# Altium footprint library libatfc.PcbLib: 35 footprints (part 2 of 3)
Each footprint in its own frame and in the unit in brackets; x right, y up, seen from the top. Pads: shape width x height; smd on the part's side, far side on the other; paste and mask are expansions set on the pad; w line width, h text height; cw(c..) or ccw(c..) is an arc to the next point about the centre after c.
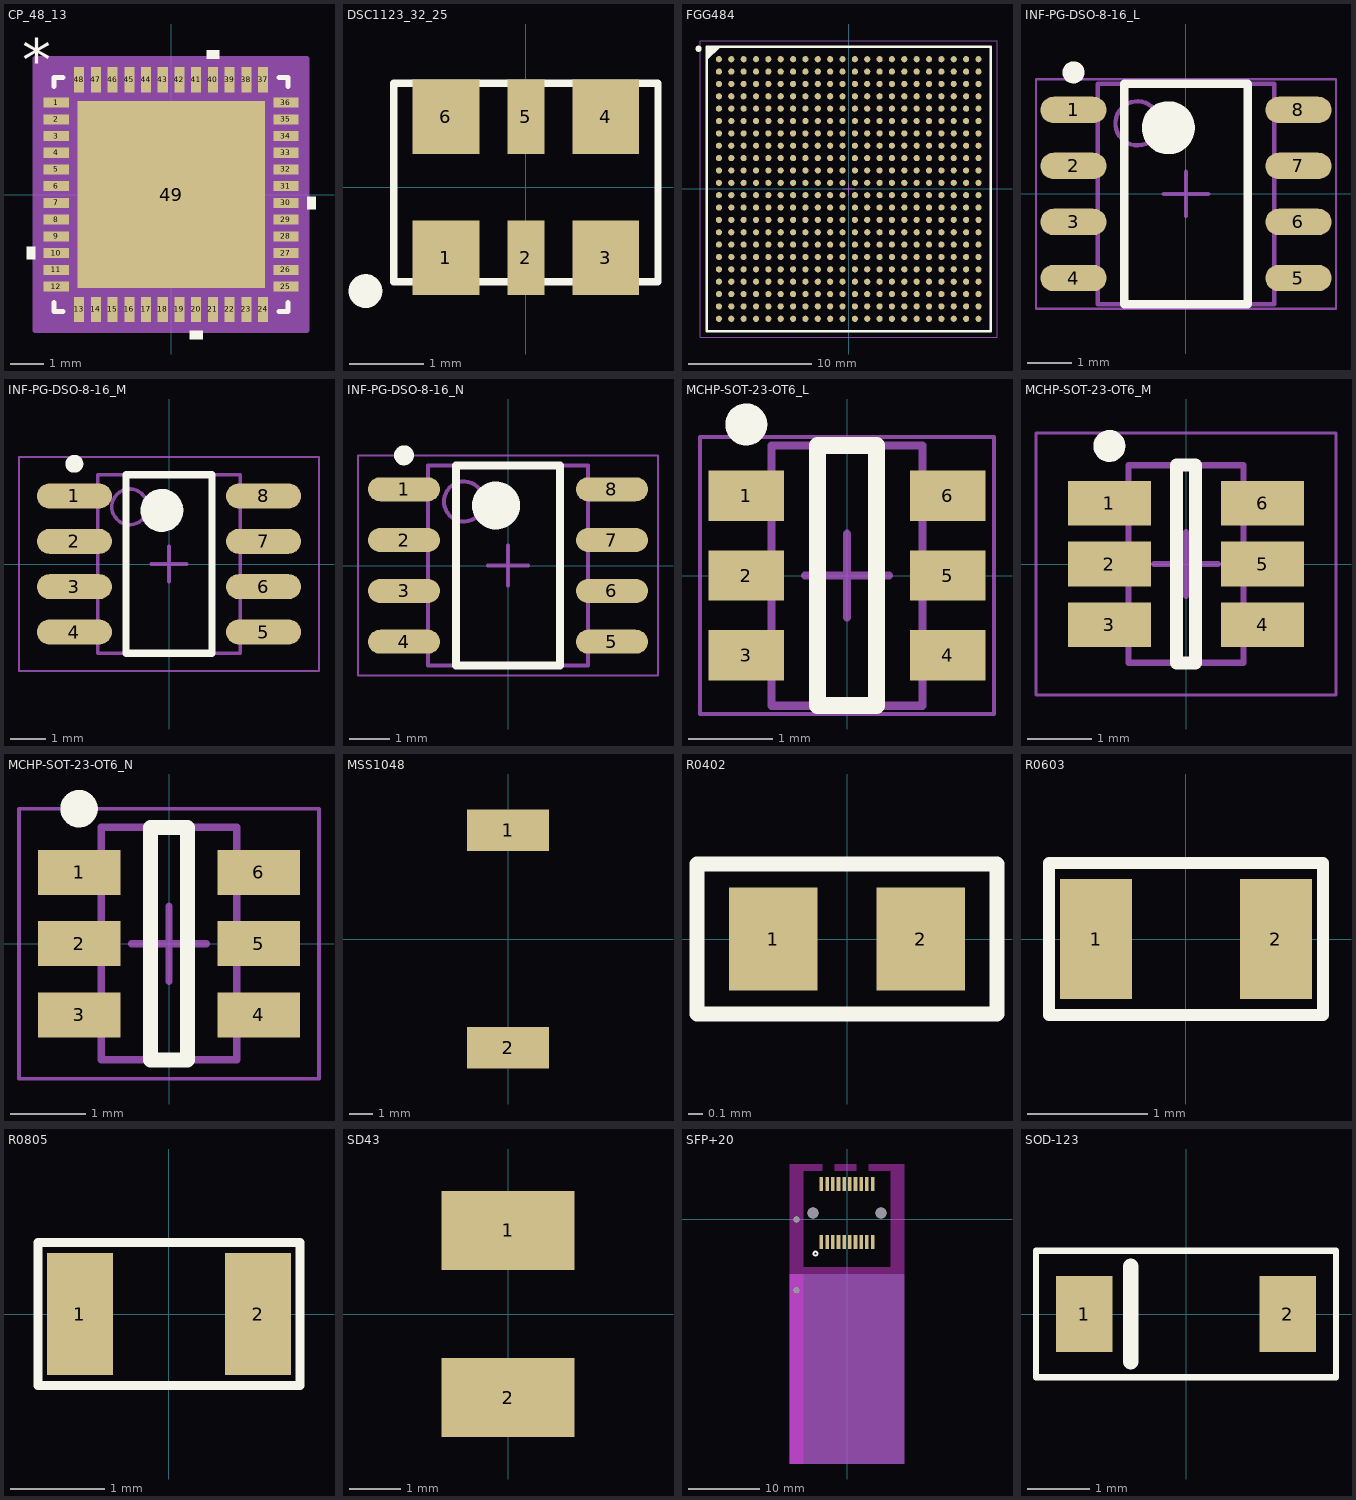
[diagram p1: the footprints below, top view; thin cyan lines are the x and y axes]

## CP_48_13 [mm]
pads (49):
  rect 0.755x0.3 smd: 1(-3.433,2.75) 2(-3.433,2.25) 3(-3.433,1.75) 4(-3.433,1.25) 5(-3.433,0.75) 6(-3.433,0.25) 7(-3.433,-0.25) 8(-3.433,-0.75) 9(-3.433,-1.25) 10(-3.433,-1.75) 11(-3.433,-2.25) 12(-3.433,-2.75) 25(3.433,-2.75) 26(3.433,-2.25) 27(3.433,-1.75) 28(3.433,-1.25) 29(3.433,-0.75) 30(3.433,-0.25) 31(3.433,0.25) 32(3.433,0.75) 33(3.433,1.25) 34(3.433,1.75) 35(3.433,2.25) 36(3.433,2.75)
  rect 0.3x0.755 smd: 13(-2.75,-3.433) 14(-2.25,-3.433) 15(-1.75,-3.433) 16(-1.25,-3.433) 17(-0.75,-3.433) 18(-0.25,-3.433) 19(0.25,-3.433) 20(0.75,-3.433) 21(1.25,-3.433) 22(1.75,-3.433) 23(2.25,-3.433) 24(2.75,-3.433) 37(2.75,3.433) 38(2.25,3.433) 39(1.75,3.433) 40(1.25,3.433) 41(0.75,3.433) 42(0.25,3.433) 43(-0.25,3.433) 44(-0.75,3.433) 45(-1.25,3.433) 46(-1.75,3.433) 47(-2.25,3.433) 48(-2.75,3.433)
  rect 5.6x5.6 smd mask-2.781: 49(0,0)
Top Overlay:
  region: -4.064,-1.559 -4.318,-1.559 -4.318,-1.94 -4.064,-1.94
  region: 0.941,-4.064 0.56,-4.064 0.56,-4.318 0.941,-4.318
  region: 4.064,-0.059 4.318,-0.059 4.318,-0.44 4.064,-0.44
  region: 1.441,4.064 1.06,4.064 1.06,4.318 1.441,4.318
  lines w0.152: -3.5,-3.233 -3.5,-3.5 -3.233,-3.5 ; -3.5,3.233 -3.5,3.5 -3.233,3.5 ; 3.233,-3.5 3.5,-3.5 3.5,-3.233 ; 3.233,3.5 3.5,3.5 3.5,3.233
  text "*" at -4.445,3.381 h1.27
Mechanical 13:
  text "*" at -4.445,3.381 h1.27
Mechanical 15:
  region: 4.064,-4.064 -4.064,-4.064 -4.064,4.064 4.064,4.064
  lines w0.152: -4.064,-4.064 -4.064,4.064 4.064,4.064 4.064,-4.064 -4.064,-4.064
3D body: height 0.25, standoff 0, extent 0,0 0.254,0.254

## DSC1123_32_25 [mm]
pads (6):
  rect 0.9x1 smd: 1(-1.075,-0.95) 3(1.075,-0.95) 4(1.075,0.95) 6(-1.075,0.95)
  rect 0.5x1 smd: 2(0,-0.95) 5(0,0.95)
Top Overlay:
  circle w0.254: c-2.159,-1.397 r0.1
  lines w0.1: -1.778,-1.27 -1.778,1.397 1.778,1.397 1.778,-1.27 -1.778,-1.27
3D body: height 0.85, standoff 0, extent -1.778,-1.27 1.778,1.397

## FGG484 [mm] "BGA, 484-Balls, Body 23x23mm, Pitch 1mm"
height 2.6
pads (484):
  round 0.5 smd: A1(-10.5,10.5) A2(-9.5,10.5) A3(-8.5,10.5) A4(-7.5,10.5) A5(-6.5,10.5) A6(-5.5,10.5) A7(-4.5,10.5) A8(-3.5,10.5) A9(-2.5,10.5) A10(-1.5,10.5) A11(-0.5,10.5) A12(0.5,10.5) A13(1.5,10.5) A14(2.5,10.5) A15(3.5,10.5) A16(4.5,10.5) A17(5.5,10.5) A18(6.5,10.5) A19(7.5,10.5) A20(8.5,10.5) A21(9.5,10.5) A22(10.5,10.5) AA1(-10.5,-9.5) AA2(-9.5,-9.5) AA3(-8.5,-9.5) AA4(-7.5,-9.5) AA5(-6.5,-9.5) AA6(-5.5,-9.5) AA7(-4.5,-9.5) AA8(-3.5,-9.5) AA9(-2.5,-9.5) AA10(-1.5,-9.5) AA11(-0.5,-9.5) AA12(0.5,-9.5) AA13(1.5,-9.5) AA14(2.5,-9.5) AA15(3.5,-9.5) AA16(4.5,-9.5) AA17(5.5,-9.5) AA18(6.5,-9.5) AA19(7.5,-9.5) AA20(8.5,-9.5) AA21(9.5,-9.5) AA22(10.5,-9.5) AB1(-10.5,-10.5) AB2(-9.5,-10.5) AB3(-8.5,-10.5) AB4(-7.5,-10.5) AB5(-6.5,-10.5) AB6(-5.5,-10.5) AB7(-4.5,-10.5) AB8(-3.5,-10.5) AB9(-2.5,-10.5) AB10(-1.5,-10.5) AB11(-0.5,-10.5) AB12(0.5,-10.5) AB13(1.5,-10.5) AB14(2.5,-10.5) AB15(3.5,-10.5) AB16(4.5,-10.5) AB17(5.5,-10.5) AB18(6.5,-10.5) AB19(7.5,-10.5) AB20(8.5,-10.5) AB21(9.5,-10.5) AB22(10.5,-10.5) B1(-10.5,9.5) B2(-9.5,9.5) B3(-8.5,9.5) B4(-7.5,9.5) B5(-6.5,9.5) B6(-5.5,9.5) B7(-4.5,9.5) B8(-3.5,9.5) B9(-2.5,9.5) B10(-1.5,9.5) B11(-0.5,9.5) B12(0.5,9.5) B13(1.5,9.5) B14(2.5,9.5) B15(3.5,9.5) B16(4.5,9.5) B17(5.5,9.5) B18(6.5,9.5) B19(7.5,9.5) B20(8.5,9.5) B21(9.5,9.5) B22(10.5,9.5) C1(-10.5,8.5) C2(-9.5,8.5) C3(-8.5,8.5) C4(-7.5,8.5) C5(-6.5,8.5) C6(-5.5,8.5) C7(-4.5,8.5) C8(-3.5,8.5) C9(-2.5,8.5) C10(-1.5,8.5) C11(-0.5,8.5) C12(0.5,8.5) C13(1.5,8.5) C14(2.5,8.5) C15(3.5,8.5) C16(4.5,8.5) C17(5.5,8.5) C18(6.5,8.5) C19(7.5,8.5) C20(8.5,8.5) C21(9.5,8.5) C22(10.5,8.5) D1(-10.5,7.5) D2(-9.5,7.5) D3(-8.5,7.5) D4(-7.5,7.5) D5(-6.5,7.5) D6(-5.5,7.5) D7(-4.5,7.5) D8(-3.5,7.5) D9(-2.5,7.5) D10(-1.5,7.5) D11(-0.5,7.5) D12(0.5,7.5) D13(1.5,7.5) D14(2.5,7.5) D15(3.5,7.5) D16(4.5,7.5) D17(5.5,7.5) D18(6.5,7.5) D19(7.5,7.5) D20(8.5,7.5) D21(9.5,7.5) D22(10.5,7.5) E1(-10.5,6.5) E2(-9.5,6.5) E3(-8.5,6.5) E4(-7.5,6.5) E5(-6.5,6.5) E6(-5.5,6.5) E7(-4.5,6.5) E8(-3.5,6.5) E9(-2.5,6.5) E10(-1.5,6.5) E11(-0.5,6.5) E12(0.5,6.5) E13(1.5,6.5) E14(2.5,6.5) E15(3.5,6.5) E16(4.5,6.5) E17(5.5,6.5) E18(6.5,6.5) E19(7.5,6.5) E20(8.5,6.5) E21(9.5,6.5) E22(10.5,6.5) F1(-10.5,5.5) F2(-9.5,5.5) F3(-8.5,5.5) F4(-7.5,5.5) F5(-6.5,5.5) F6(-5.5,5.5) F7(-4.5,5.5) F8(-3.5,5.5) F9(-2.5,5.5) F10(-1.5,5.5) F11(-0.5,5.5) F12(0.5,5.5) F13(1.5,5.5) F14(2.5,5.5) F15(3.5,5.5) F16(4.5,5.5) F17(5.5,5.5) F18(6.5,5.5) F19(7.5,5.5) F20(8.5,5.5) F21(9.5,5.5) F22(10.5,5.5) G1(-10.5,4.5) G2(-9.5,4.5) G3(-8.5,4.5) G4(-7.5,4.5) G5(-6.5,4.5) G6(-5.5,4.5) G7(-4.5,4.5) G8(-3.5,4.5) G9(-2.5,4.5) G10(-1.5,4.5) G11(-0.5,4.5) G12(0.5,4.5) G13(1.5,4.5) G14(2.5,4.5) G15(3.5,4.5) G16(4.5,4.5) G17(5.5,4.5) G18(6.5,4.5) G19(7.5,4.5) G20(8.5,4.5) G21(9.5,4.5) G22(10.5,4.5) H1(-10.5,3.5) H2(-9.5,3.5) H3(-8.5,3.5) H4(-7.5,3.5) H5(-6.5,3.5) H6(-5.5,3.5) H7(-4.5,3.5) H8(-3.5,3.5) H9(-2.5,3.5) H10(-1.5,3.5) H11(-0.5,3.5) H12(0.5,3.5) H13(1.5,3.5) H14(2.5,3.5) H15(3.5,3.5) H16(4.5,3.5) H17(5.5,3.5) H18(6.5,3.5) H19(7.5,3.5) H20(8.5,3.5) H21(9.5,3.5) H22(10.5,3.5) J1(-10.5,2.5) J2(-9.5,2.5) J3(-8.5,2.5) J4(-7.5,2.5) J5(-6.5,2.5) J6(-5.5,2.5) J7(-4.5,2.5) J8(-3.5,2.5) J9(-2.5,2.5) J10(-1.5,2.5) J11(-0.5,2.5) J12(0.5,2.5) J13(1.5,2.5) J14(2.5,2.5) J15(3.5,2.5) J16(4.5,2.5) J17(5.5,2.5) J18(6.5,2.5) J19(7.5,2.5) J20(8.5,2.5) J21(9.5,2.5) J22(10.5,2.5) K1(-10.5,1.5) K2(-9.5,1.5) K3(-8.5,1.5) K4(-7.5,1.5) K5(-6.5,1.5) K6(-5.5,1.5) K7(-4.5,1.5) K8(-3.5,1.5) K9(-2.5,1.5) K10(-1.5,1.5) K11(-0.5,1.5) K12(0.5,1.5) K13(1.5,1.5) K14(2.5,1.5) K15(3.5,1.5) K16(4.5,1.5) K17(5.5,1.5) K18(6.5,1.5) K19(7.5,1.5) K20(8.5,1.5) K21(9.5,1.5) K22(10.5,1.5) L1(-10.5,0.5) L2(-9.5,0.5) L3(-8.5,0.5) L4(-7.5,0.5) L5(-6.5,0.5) L6(-5.5,0.5) L7(-4.5,0.5) L8(-3.5,0.5) L9(-2.5,0.5) L10(-1.5,0.5) L11(-0.5,0.5) L12(0.5,0.5) L13(1.5,0.5) L14(2.5,0.5) L15(3.5,0.5) L16(4.5,0.5) L17(5.5,0.5) L18(6.5,0.5) L19(7.5,0.5) L20(8.5,0.5) L21(9.5,0.5) L22(10.5,0.5) M1(-10.5,-0.5) M2(-9.5,-0.5) M3(-8.5,-0.5) M4(-7.5,-0.5) M5(-6.5,-0.5) M6(-5.5,-0.5) M7(-4.5,-0.5) M8(-3.5,-0.5) M9(-2.5,-0.5) M10(-1.5,-0.5) M11(-0.5,-0.5) M12(0.5,-0.5) M13(1.5,-0.5) M14(2.5,-0.5) M15(3.5,-0.5) M16(4.5,-0.5) M17(5.5,-0.5) M18(6.5,-0.5) M19(7.5,-0.5) M20(8.5,-0.5) M21(9.5,-0.5) M22(10.5,-0.5) N1(-10.5,-1.5) N2(-9.5,-1.5) N3(-8.5,-1.5) N4(-7.5,-1.5) N5(-6.5,-1.5) N6(-5.5,-1.5) N7(-4.5,-1.5) N8(-3.5,-1.5) N9(-2.5,-1.5) N10(-1.5,-1.5) N11(-0.5,-1.5) N12(0.5,-1.5) N13(1.5,-1.5) N14(2.5,-1.5) N15(3.5,-1.5) N16(4.5,-1.5) N17(5.5,-1.5) N18(6.5,-1.5) N19(7.5,-1.5) N20(8.5,-1.5) N21(9.5,-1.5) N22(10.5,-1.5) P1(-10.5,-2.5) P2(-9.5,-2.5) P3(-8.5,-2.5) P4(-7.5,-2.5) P5(-6.5,-2.5) P6(-5.5,-2.5) P7(-4.5,-2.5) P8(-3.5,-2.5) P9(-2.5,-2.5) P10(-1.5,-2.5) P11(-0.5,-2.5) P12(0.5,-2.5) P13(1.5,-2.5) P14(2.5,-2.5) P15(3.5,-2.5) P16(4.5,-2.5) P17(5.5,-2.5) P18(6.5,-2.5) P19(7.5,-2.5) P20(8.5,-2.5) P21(9.5,-2.5) P22(10.5,-2.5) R1(-10.5,-3.5) R2(-9.5,-3.5) R3(-8.5,-3.5) R4(-7.5,-3.5) R5(-6.5,-3.5) R6(-5.5,-3.5) R7(-4.5,-3.5) R8(-3.5,-3.5) R9(-2.5,-3.5) R10(-1.5,-3.5) R11(-0.5,-3.5) R12(0.5,-3.5) R13(1.5,-3.5) R14(2.5,-3.5) R15(3.5,-3.5) R16(4.5,-3.5) R17(5.5,-3.5) R18(6.5,-3.5) R19(7.5,-3.5) R20(8.5,-3.5) R21(9.5,-3.5) R22(10.5,-3.5) T1(-10.5,-4.5) T2(-9.5,-4.5) T3(-8.5,-4.5) T4(-7.5,-4.5) T5(-6.5,-4.5) T6(-5.5,-4.5) T7(-4.5,-4.5) T8(-3.5,-4.5) T9(-2.5,-4.5) T10(-1.5,-4.5) T11(-0.5,-4.5) T12(0.5,-4.5) T13(1.5,-4.5) T14(2.5,-4.5) T15(3.5,-4.5) T16(4.5,-4.5) T17(5.5,-4.5) T18(6.5,-4.5) T19(7.5,-4.5) T20(8.5,-4.5) T21(9.5,-4.5) T22(10.5,-4.5) U1(-10.5,-5.5) U2(-9.5,-5.5) U3(-8.5,-5.5) U4(-7.5,-5.5) U5(-6.5,-5.5) U6(-5.5,-5.5) U7(-4.5,-5.5) U8(-3.5,-5.5) U9(-2.5,-5.5) U10(-1.5,-5.5) U11(-0.5,-5.5) U12(0.5,-5.5) U13(1.5,-5.5) U14(2.5,-5.5) U15(3.5,-5.5) U16(4.5,-5.5) U17(5.5,-5.5) U18(6.5,-5.5) U19(7.5,-5.5) U20(8.5,-5.5) U21(9.5,-5.5) U22(10.5,-5.5) V1(-10.5,-6.5) V2(-9.5,-6.5) V3(-8.5,-6.5) V4(-7.5,-6.5) V5(-6.5,-6.5) V6(-5.5,-6.5) V7(-4.5,-6.5) V8(-3.5,-6.5) V9(-2.5,-6.5) V10(-1.5,-6.5) V11(-0.5,-6.5) V12(0.5,-6.5) V13(1.5,-6.5) V14(2.5,-6.5) V15(3.5,-6.5) V16(4.5,-6.5) V17(5.5,-6.5) V18(6.5,-6.5) V19(7.5,-6.5) V20(8.5,-6.5) V21(9.5,-6.5) V22(10.5,-6.5) W1(-10.5,-7.5) W2(-9.5,-7.5) W3(-8.5,-7.5) W4(-7.5,-7.5) W5(-6.5,-7.5) W6(-5.5,-7.5) W7(-4.5,-7.5) W8(-3.5,-7.5) W9(-2.5,-7.5) W10(-1.5,-7.5) W11(-0.5,-7.5) W12(0.5,-7.5) W13(1.5,-7.5) W14(2.5,-7.5) W15(3.5,-7.5) W16(4.5,-7.5) W17(5.5,-7.5) W18(6.5,-7.5) W19(7.5,-7.5) W20(8.5,-7.5) W21(9.5,-7.5) W22(10.5,-7.5) Y1(-10.5,-8.5) Y2(-9.5,-8.5) Y3(-8.5,-8.5) Y4(-7.5,-8.5) Y5(-6.5,-8.5) Y6(-5.5,-8.5) Y7(-4.5,-8.5) Y8(-3.5,-8.5) Y9(-2.5,-8.5) Y10(-1.5,-8.5) Y11(-0.5,-8.5) Y12(0.5,-8.5) Y13(1.5,-8.5) Y14(2.5,-8.5) Y15(3.5,-8.5) Y16(4.5,-8.5) Y17(5.5,-8.5) Y18(6.5,-8.5) Y19(7.5,-8.5) Y20(8.5,-8.5) Y21(9.5,-8.5) Y22(10.5,-8.5)
Top Overlay:
  circle w0.25: c-12.15,11.35 r0.125
  region: -10.5,11.5 -11.5,10.5 -11.5,11.5
  lines w0.2: -11.5,10.5 -10.5,11.5 ; -11.5,-11.5 11.5,-11.5 11.5,11.5 -11.5,11.5 -11.5,-11.5
Mechanical 13:
  lines w0.1: -11.5,-11.5 11.5,-11.5 11.5,11.5 -11.5,11.5 -11.5,-11.5
Mechanical 15:
  lines w0.05: -12,-12 12,-12 12,12 -12,12 -12,-12
  lines w0.1: -0.5,0 0.5,0 ; 0,-0.5 0,0.5
3D body: height 2.6, standoff 0.35, extent -11.5,-11.5 11.5,11.5

## INF-PG-DSO-8-16_L [mm] "SOP, 8-Leads, Body 4.9x3.9mm, Pitch 1.27mm, IPC High Density"
height 1.75
pads (8):
  oval 1.5x0.6 smd: 1(-2.55,1.905) 2(-2.55,0.635) 3(-2.55,-0.635) 4(-2.55,-1.905) 5(2.55,-1.905) 6(2.55,-0.635) 7(2.55,0.635) 8(2.55,1.905)
Top Overlay:
  circle w0.6: c-0.4,1.5 r0.3
  circle w0.25: c-2.55,2.755 r0.125
  lines w0.2: -1.4,-2.5 1.4,-2.5 1.4,2.5 -1.4,2.5 -1.4,-2.5
Mechanical 13:
  circle w0.1: c-1.1,1.6 r0.5
  lines w0.1: -2,-2.5 2,-2.5 2,2.5 -2,2.5 -2,-2.5
Mechanical 15:
  lines w0.05: -3.4,-2.6 3.4,-2.6 3.4,2.6 -3.4,2.6 -3.4,-2.6
  lines w0.1: -0.5,0 0.5,0 ; 0,-0.5 0,0.5
3D body: height 1.75, standoff 0.11, extent -2,-2.5 2,2.5

## INF-PG-DSO-8-16_M [mm] "SOP, 8-Leads, Body 4.9x3.9mm, Pitch 1.27mm, IPC Low Density"
height 1.75
pads (8):
  oval 2.1x0.7 smd: 1(-2.65,1.905) 2(-2.65,0.635) 3(-2.65,-0.635) 4(-2.65,-1.905) 5(2.65,-1.905) 6(2.65,-0.635) 7(2.65,0.635) 8(2.65,1.905)
Top Overlay:
  circle w0.25: c-2.65,2.805 r0.125
  circle w0.6: c-0.2,1.5 r0.3
  lines w0.2: -1.2,-2.5 -1.2,2.5 1.2,2.5 1.2,-2.5 -1.2,-2.5
Mechanical 13:
  circle w0.1: c-1.1,1.6 r0.5
  lines w0.1: -2,-2.5 -2,2.5 2,2.5 2,-2.5 -2,-2.5
Mechanical 15:
  lines w0.05: -4.2,-3 -4.2,3 4.2,3 4.2,-3 -4.2,-3
  lines w0.1: -0.5,0 0.5,0 ; 0,-0.5 0,0.5
3D body: height 1.75, standoff 0.11, extent -2,-2.5 2,2.5

## INF-PG-DSO-8-16_N [mm] "SOP, 8-Leads, Body 4.9x3.9mm, Pitch 1.27mm, IPC Medium Density"
height 1.75
pads (8):
  oval 1.8x0.6 smd: 1(-2.6,1.905) 2(-2.6,0.635) 3(-2.6,-0.635) 4(-2.6,-1.905) 5(2.6,-1.905) 6(2.6,-0.635) 7(2.6,0.635) 8(2.6,1.905)
Top Overlay:
  circle w0.6: c-0.3,1.5 r0.3
  circle w0.25: c-2.6,2.755 r0.125
  lines w0.2: -1.3,-2.5 1.3,-2.5 1.3,2.5 -1.3,2.5 -1.3,-2.5
Mechanical 13:
  circle w0.1: c-1.1,1.6 r0.5
  lines w0.1: -2,-2.5 2,-2.5 2,2.5 -2,2.5 -2,-2.5
Mechanical 15:
  lines w0.05: -3.75,-2.75 3.75,-2.75 3.75,2.75 -3.75,2.75 -3.75,-2.75
  lines w0.1: -0.5,0 0.5,0 ; 0,-0.5 0,0.5
3D body: height 1.75, standoff 0.11, extent -2,-2.5 2,2.5

## MCHP-SOT-23-OT6_L [mm] "SOT23, 6-Leads, Body 2.9x1.55mm, Pitch 0.95mm, IPC High Density"
height 1.45
pads (6):
  rect 0.9x0.6 smd: 1(-1.2,0.95) 2(-1.2,0) 3(-1.2,-0.95) 4(1.2,-0.95) 5(1.2,0) 6(1.2,0.95)
Top Overlay:
  circle w0.25: c-1.2,1.8 r0.125
  lines w0.2: -0.35,-1.55 0.35,-1.55 0.35,1.55 -0.35,1.55 -0.35,-1.55
Mechanical 13:
  lines w0.1: -0.9,-1.55 -0.9,1.55 0.9,1.55 0.9,-1.55 -0.9,-1.55
Mechanical 15:
  lines w0.05: -1.75,-1.65 -1.75,1.65 1.75,1.65 1.75,-1.65 -1.75,-1.65
  lines w0.1: -0.5,0 0.5,0 ; 0,-0.5 0,0.5
3D body: height 1.45, standoff 0, extent -0.9,-1.55 0.9,1.55

## MCHP-SOT-23-OT6_M [mm] "SOT23, 6-Leads, Body 2.9x1.55mm, Pitch 0.95mm, IPC Low Density"
height 1.45
pads (6):
  rect 1.3x0.7 smd: 1(-1.2,0.95) 2(-1.2,0) 3(-1.2,-0.95) 4(1.2,-0.95) 5(1.2,0) 6(1.2,0.95)
Top Overlay:
  circle w0.25: c-1.2,1.85 r0.125
  lines w0.2: -0.15,-1.55 -0.15,1.55 0.15,1.55 0.15,-1.55 -0.15,-1.55
Mechanical 13:
  lines w0.1: -0.9,-1.55 0.9,-1.55 0.9,1.55 -0.9,1.55 -0.9,-1.55
Mechanical 15:
  lines w0.05: -2.35,-2.05 2.35,-2.05 2.35,2.05 -2.35,2.05 -2.35,-2.05
  lines w0.1: -0.5,0 0.5,0 ; 0,-0.5 0,0.5
3D body: height 1.45, standoff 0, extent -0.9,-1.55 0.9,1.55

## MCHP-SOT-23-OT6_N [mm] "SOT23, 6-Leads, Body 2.9x1.55mm, Pitch 0.95mm, IPC Medium Density"
height 1.45
pads (6):
  rect 1.1x0.6 smd: 1(-1.2,0.95) 2(-1.2,0) 3(-1.2,-0.95) 4(1.2,-0.95) 5(1.2,0) 6(1.2,0.95)
Top Overlay:
  circle w0.25: c-1.2,1.8 r0.125
  lines w0.2: -0.25,-1.55 0.25,-1.55 0.25,1.55 -0.25,1.55 -0.25,-1.55
Mechanical 13:
  lines w0.1: -0.9,-1.55 -0.9,1.55 0.9,1.55 0.9,-1.55 -0.9,-1.55
Mechanical 15:
  lines w0.05: -2,-1.8 -2,1.8 2,1.8 2,-1.8 -2,-1.8
  lines w0.1: -0.5,0 0.5,0 ; 0,-0.5 0,0.5
3D body: height 1.45, standoff 0, extent -0.9,-1.55 0.9,1.55

## MSS1048 [mm]
pads (2):
  rect 3.56x1.78 smd: 1(0,4.7) 2(0,-4.7)
3D body "Coilcraft-MSS1048.step": height 5, standoff -0.1, extent -5.227,-5.15 4.973,5.15

## R0402 [mm]
pads (2):
  rect 0.6x0.7 smd: 1(-0.5,0) 2(0.5,0)
Top Overlay:
  lines w0.1: -1.016,-0.508 1.016,-0.508 1.016,0.508 -1.016,0.508 -1.016,-0.508
3D body: height 0.35, standoff 0, extent -0.54,-0.254 -0.381,0.254
3D body: height 0.35, standoff 0, extent -0.381,-0.254 0.381,0.254
3D body: height 0.35, standoff 0, extent 0.381,-0.254 0.54,0.254

## R0603 [mm]
pads (2):
  rect 0.6x1 smd: 1(-0.75,0) 2(0.75,0)
Top Overlay:
  lines w0.1: -1.143,-0.635 -1.143,0.635 1.143,0.635 1.143,-0.635 -1.143,-0.635
3D body: height 0.35, standoff 0, extent -0.762,-0.444 -0.508,0.445
3D body: height 0.35, standoff 0, extent 0.508,-0.444 0.762,0.445
3D body: height 0.35, standoff 0, extent -0.508,-0.444 0.508,0.445

## R0805 [mm]
pads (2):
  rect 0.7x1.3 smd: 1(-0.95,0) 2(0.95,0)
Top Overlay:
  lines w0.1: -1.397,-0.762 -1.397,-0.253 -1.397,0.762 1.397,0.762 1.397,-0.762 -1.397,-0.762
3D body: height 0.35, standoff 0, extent -1.016,-0.603 -0.762,0.603
3D body: height 0.35, standoff 0, extent -0.762,-0.603 0.762,0.603
3D body: height 0.35, standoff 0, extent 0.762,-0.603 1.016,0.603

## SD43 [mm]
pads (2):
  rect 2.6x1.55 smd: 1(0,1.64) 2(0,-1.64)
3D body "Coilcraft-SD43.STEP": height 3.45, standoff 0, extent -2.1,-2.314 2.1,2.314

## SFP+20 [mm]
pads (24):
  rect 0.5x2 smd: 1(-3.6,-3.2) 2(-2.8,-3.2) 3(-2,-3.2) 4(-1.2,-3.2) 5(-0.4,-3.2) 6(0.4,-3.2) 7(1.2,-3.2) 8(2,-3.2) 9(2.8,-3.2) 10(3.6,-3.2) 11(3.6,5) 12(2.8,5) 13(2,5) 14(1.2,5) 15(0.4,5) 16(-0.4,5) 17(-1.2,5) 18(-2,5) 19(-2.8,5) 20(-3.6,5)
  round 0.85 hole 0.85 paste+0 mask+0: ""(-7.13,-10) ""(-7.13,0)
  round 1.55 hole 1.55 paste+0 mask+0: ""(-4.8,0.9) ""(4.8,0.9)
Top Overlay:
  circle w0.254: c-4.445,-4.826 r0.284
Keep-Out Layer:
  rectangle: -1.75,6.8 1.35,7.8
  rectangle: -8.13,-7.7 8.13,-6.7
  rectangle: -8.13,6.8 -3.45,7.8
  rectangle: 3.05,6.8 8.12,7.8
Keep-Out Layer:
  rectangle: -8.13,-34.5 -6.13,7.8
  rectangle: 6.13,-7.7 8.12,7.8
Mechanical 1:
  rectangle: -8.13,-34.5 8.12,-7.7

## SOD-123 [mm]
pads (2):
  rect 0.91x1.22 smd: 1(-1.635,0) 2(1.635,0)
Top Overlay:
  lines w0.1: -2.413,-1.016 -0.889,-1.016 2.413,-1.016 2.413,1.016 -0.889,1.016 -2.413,1.016 -2.413,-1.016
  lines w0.254: -0.889,-0.762 -0.889,0.762
3D body: height 1.17, standoff 0, extent -1.27,-0.635 1.27,0.635
3D body: height 0.15, standoff 0, extent -1.651,-0.381 -1.27,0.381
3D body: height 0.15, standoff 0, extent 1.27,-0.381 1.651,0.381
3D body: height 1.18, standoff 1.17, extent -1.016,-0.635 -0.762,0.635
